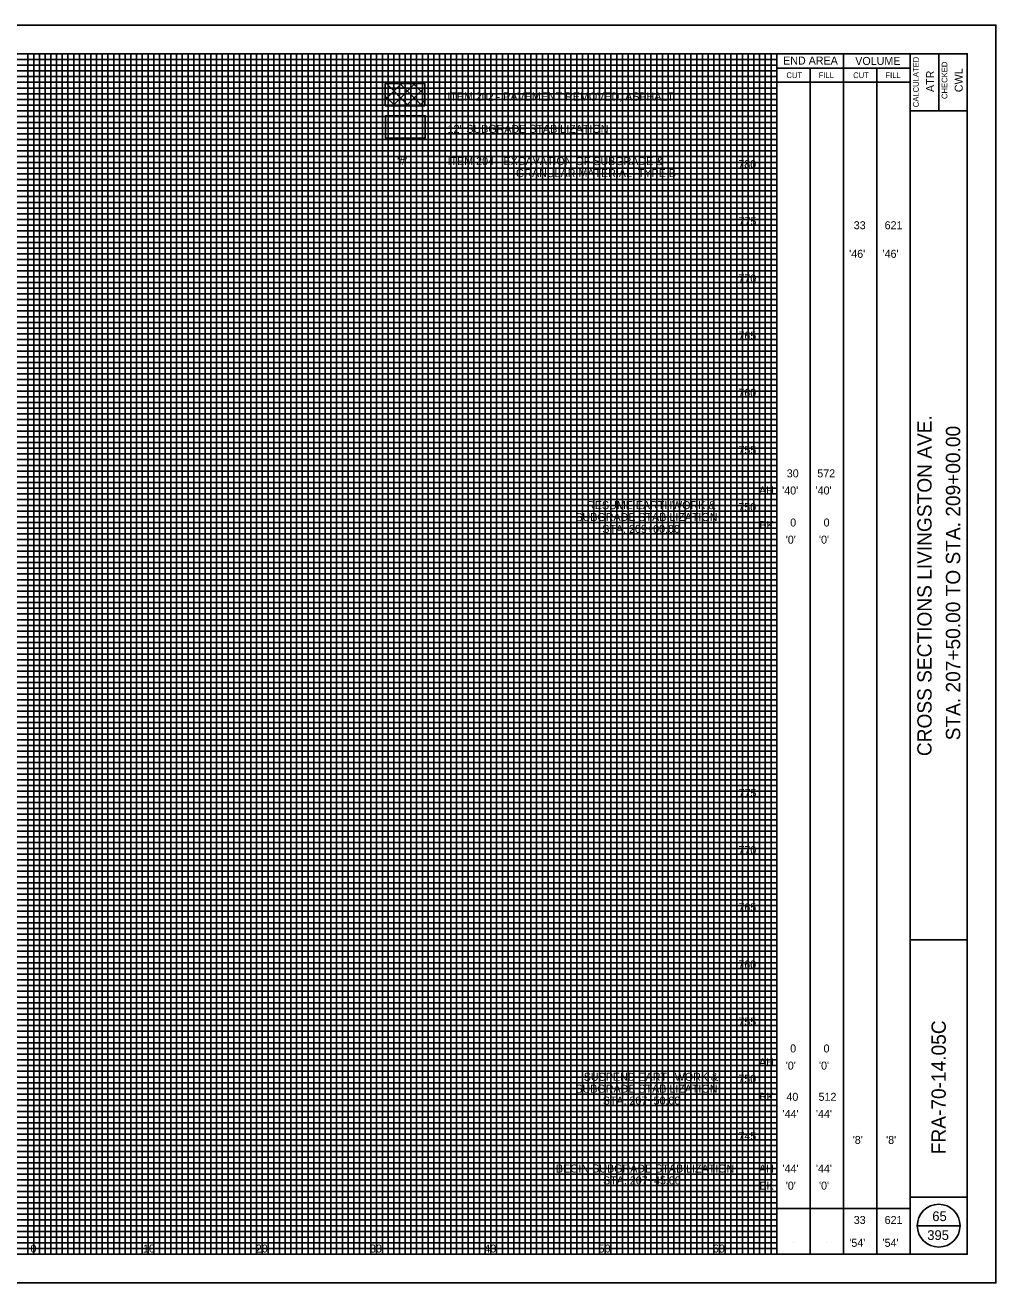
# Model space of a CAD drawing. Extents: x -10 to 160, y -2 to 568.
# Drawn here: x 75.1 to 160, y 227.5 to 337.5 of the extents above; entities that cross this region are included whole.
import ezdxf

# ---------------------------------------------------------------- set-up
doc = ezdxf.new("R2010")
doc.units = 0
for name, color, linetype in [('DR_P_Text', 7, 'Continuous'), ('SH_Border', 7, 'Continuous'), ('SH_Cut_Line', 7, 'Continuous'), ('SH_Data', 7, 'Continuous'), ('SH_Major_Grid_Line', 7, 'Continuous'), ('SH_Minor_Grid_Line', 7, 'Continuous'), ('XS_P_Annotation', 7, 'Continuous'), ('XS_P_Undercut', 7, 'Continuous'), ('XS_X_Pavt', 7, 'Continuous')]:
    doc.layers.add(name, color=color, linetype=linetype)

msp = doc.modelspace()

# ---------------------------------------------------------------- linework, layer by layer
at = {"layer": 'SH_Border'}
for p, q in [((152.5, 230), (152.5, 335)), ((155, 335), (155, 330)), ((152.5, 330), (157.5, 330)), ((152.5, 257.5), (157.5, 257.5)), ((152.5, 235), (157.5, 235))]:
    msp.add_line(p, q, dxfattribs=at)
msp.add_lwpolyline([(0, 335), (157.5, 335), (157.5, 230), (0, 230)], close=True, dxfattribs=at)
at = {"layer": 'SH_Cut_Line'}
msp.add_lwpolyline([(-10, 227.5), (160, 227.5), (160, 337.5), (-10, 337.5)], close=True, dxfattribs=at)
at = {"layer": 'SH_Data'}
for p, q in [((140.83, 230), (140.83, 335)), ((146.67, 230), (146.67, 335)), ((140.83, 333.75), (152.5, 333.75)), ((143.75, 230), (143.75, 333.75)), ((149.58, 230), (149.58, 333.75)), ((140.83, 332.5), (152.5, 332.5)), ((140.83, 234), (152.5, 234)), ((153.12, 232.5), (156.88, 232.5)), ((142.29, 231), (142.29, 231)), ((145.21, 231), (145.21, 231)), ((148.12, 231), (148.12, 231)), ((151.04, 231), (151.04, 231))]:
    msp.add_line(p, q, dxfattribs=at)
msp.add_circle((155, 232.5), 1.87, dxfattribs=at)
at = {"layer": 'SH_Major_Grid_Line'}
for p, q in [((75.83, 230), (75.83, 335)), ((80.83, 230), (80.83, 335)), ((85.83, 230), (85.83, 335)), ((90.83, 230), (90.83, 335)), ((95.83, 230), (95.83, 335)), ((100.83, 230), (100.83, 335)), ((105.83, 230), (105.83, 335)), ((110.83, 230), (110.83, 335)), ((115.83, 230), (115.83, 335)), ((120.83, 230), (120.83, 335)), ((125.83, 230), (125.83, 335)), ((130.83, 230), (130.83, 335)), ((135.83, 230), (135.83, 335)), ((5.83, 330), (140.83, 330)), ((5.83, 325), (140.83, 325)), ((5.83, 320), (140.83, 320)), ((5.83, 315), (140.83, 315)), ((5.83, 310), (140.83, 310)), ((5.83, 305), (140.83, 305)), ((5.83, 300), (140.83, 300)), ((5.83, 295), (140.83, 295)), ((5.83, 290), (140.83, 290)), ((5.83, 285), (140.83, 285)), ((5.83, 280), (140.83, 280)), ((5.83, 275), (140.83, 275)), ((5.83, 270), (140.83, 270)), ((5.83, 265), (140.83, 265)), ((5.83, 260), (140.83, 260)), ((5.83, 255), (140.83, 255)), ((5.83, 250), (140.83, 250)), ((5.83, 245), (140.83, 245)), ((5.83, 240), (140.83, 240)), ((5.83, 235), (140.83, 235))]:
    msp.add_line(p, q, dxfattribs=at)
at = {"layer": 'SH_Minor_Grid_Line'}
for p, q in [((5.83, 334.5), (140.83, 334.5)), ((75.33, 230), (75.33, 335)), ((76.33, 230), (76.33, 335)), ((76.83, 230), (76.83, 335)), ((77.33, 230), (77.33, 335)), ((77.83, 230), (77.83, 335)), ((78.33, 230), (78.33, 335)), ((78.83, 230), (78.83, 335)), ((79.33, 230), (79.33, 335)), ((79.83, 230), (79.83, 335)), ((80.33, 230), (80.33, 335)), ((81.33, 230), (81.33, 335)), ((81.83, 230), (81.83, 335)), ((82.33, 230), (82.33, 335)), ((82.83, 230), (82.83, 335)), ((83.33, 230), (83.33, 335)), ((83.83, 230), (83.83, 335)), ((84.33, 230), (84.33, 335)), ((84.83, 230), (84.83, 335)), ((85.33, 230), (85.33, 335)), ((86.33, 230), (86.33, 335)), ((86.83, 230), (86.83, 335)), ((87.33, 230), (87.33, 335)), ((87.83, 230), (87.83, 335)), ((88.33, 230), (88.33, 335)), ((88.83, 230), (88.83, 335)), ((89.33, 230), (89.33, 335)), ((89.83, 230), (89.83, 335)), ((90.33, 230), (90.33, 335)), ((91.33, 230), (91.33, 335)), ((91.83, 230), (91.83, 335)), ((92.33, 230), (92.33, 335)), ((92.83, 230), (92.83, 335)), ((93.33, 230), (93.33, 335)), ((93.83, 230), (93.83, 335)), ((94.33, 230), (94.33, 335)), ((94.83, 230), (94.83, 335)), ((95.33, 230), (95.33, 335)), ((96.33, 230), (96.33, 335)), ((96.83, 230), (96.83, 335)), ((97.33, 230), (97.33, 335)), ((97.83, 230), (97.83, 335)), ((98.33, 230), (98.33, 335)), ((98.83, 230), (98.83, 335)), ((99.33, 230), (99.33, 335)), ((99.83, 230), (99.83, 335)), ((100.33, 230), (100.33, 335)), ((101.33, 230), (101.33, 335)), ((101.83, 230), (101.83, 335)), ((102.33, 230), (102.33, 335)), ((102.83, 230), (102.83, 335)), ((103.33, 230), (103.33, 335)), ((103.83, 230), (103.83, 335)), ((104.33, 230), (104.33, 335)), ((104.83, 230), (104.83, 335)), ((105.33, 230), (105.33, 335)), ((106.33, 230), (106.33, 335)), ((106.83, 230), (106.83, 335)), ((107.33, 230), (107.33, 335)), ((107.83, 230), (107.83, 335)), ((108.33, 230), (108.33, 335)), ((108.83, 230), (108.83, 335)), ((109.33, 230), (109.33, 335)), ((109.83, 230), (109.83, 335)), ((110.33, 230), (110.33, 335)), ((111.33, 230), (111.33, 335)), ((111.83, 230), (111.83, 335)), ((112.33, 230), (112.33, 335)), ((112.83, 230), (112.83, 335)), ((113.33, 230), (113.33, 335)), ((113.83, 230), (113.83, 335)), ((114.33, 230), (114.33, 335)), ((114.83, 230), (114.83, 335)), ((115.33, 230), (115.33, 335)), ((116.33, 230), (116.33, 335)), ((116.83, 230), (116.83, 335)), ((117.33, 230), (117.33, 335)), ((117.83, 230), (117.83, 335)), ((118.33, 230), (118.33, 335)), ((118.83, 230), (118.83, 335)), ((119.33, 230), (119.33, 335)), ((119.83, 230), (119.83, 335)), ((120.33, 230), (120.33, 335)), ((121.33, 230), (121.33, 335)), ((121.83, 230), (121.83, 335)), ((122.33, 230), (122.33, 335)), ((122.83, 230), (122.83, 335)), ((123.33, 230), (123.33, 335)), ((123.83, 230), (123.83, 335)), ((124.33, 230), (124.33, 335)), ((124.83, 230), (124.83, 335)), ((125.33, 230), (125.33, 335)), ((126.33, 230), (126.33, 335)), ((126.83, 230), (126.83, 335)), ((127.33, 230), (127.33, 335)), ((127.83, 230), (127.83, 335)), ((128.33, 230), (128.33, 335)), ((128.83, 230), (128.83, 335)), ((129.33, 230), (129.33, 335)), ((129.83, 230), (129.83, 335)), ((130.33, 230), (130.33, 335)), ((131.33, 230), (131.33, 335)), ((131.83, 230), (131.83, 335)), ((132.33, 230), (132.33, 335)), ((132.83, 230), (132.83, 335)), ((133.33, 230), (133.33, 335)), ((133.83, 230), (133.83, 335)), ((134.33, 230), (134.33, 335)), ((134.83, 230), (134.83, 335)), ((135.33, 230), (135.33, 335)), ((136.33, 230), (136.33, 335)), ((136.83, 230), (136.83, 335)), ((137.33, 230), (137.33, 335)), ((137.83, 230), (137.83, 335)), ((138.33, 230), (138.33, 335)), ((138.83, 230), (138.83, 335)), ((139.33, 230), (139.33, 335)), ((139.83, 230), (139.83, 335)), ((140.33, 230), (140.33, 335)), ((5.83, 334), (140.83, 334)), ((5.83, 333.5), (140.83, 333.5)), ((5.83, 333), (140.83, 333)), ((5.83, 332.5), (140.83, 332.5)), ((5.83, 332), (140.83, 332)), ((5.83, 331.5), (140.83, 331.5)), ((5.83, 331), (140.83, 331)), ((5.83, 330.5), (140.83, 330.5)), ((5.83, 329.5), (140.83, 329.5)), ((5.83, 329), (140.83, 329)), ((5.83, 328.5), (140.83, 328.5)), ((5.83, 328), (140.83, 328)), ((5.83, 327.5), (140.83, 327.5)), ((5.83, 327), (140.83, 327)), ((5.83, 326.5), (140.83, 326.5)), ((5.83, 326), (140.83, 326)), ((5.83, 325.5), (140.83, 325.5)), ((5.83, 324.5), (140.83, 324.5)), ((5.83, 324), (140.83, 324)), ((5.83, 323.5), (140.83, 323.5)), ((5.83, 323), (140.83, 323)), ((5.83, 322.5), (140.83, 322.5)), ((5.83, 322), (140.83, 322)), ((5.83, 321.5), (140.83, 321.5)), ((5.83, 321), (140.83, 321)), ((5.83, 320.5), (140.83, 320.5)), ((5.83, 319.5), (140.83, 319.5)), ((5.83, 319), (140.83, 319)), ((5.83, 318.5), (140.83, 318.5)), ((5.83, 318), (140.83, 318)), ((5.83, 317.5), (140.83, 317.5)), ((5.83, 317), (140.83, 317)), ((5.83, 316.5), (140.83, 316.5)), ((5.83, 316), (140.83, 316)), ((5.83, 315.5), (140.83, 315.5)), ((5.83, 314.5), (140.83, 314.5)), ((5.83, 314), (140.83, 314)), ((5.83, 313.5), (140.83, 313.5)), ((5.83, 313), (140.83, 313)), ((5.83, 312.5), (140.83, 312.5)), ((5.83, 312), (140.83, 312)), ((5.83, 311.5), (140.83, 311.5)), ((5.83, 311), (140.83, 311)), ((5.83, 310.5), (140.83, 310.5)), ((5.83, 309.5), (140.83, 309.5)), ((5.83, 309), (140.83, 309)), ((5.83, 308.5), (140.83, 308.5)), ((5.83, 308), (140.83, 308)), ((5.83, 307.5), (140.83, 307.5)), ((5.83, 307), (140.83, 307)), ((5.83, 306.5), (140.83, 306.5)), ((5.83, 306), (140.83, 306)), ((5.83, 305.5), (140.83, 305.5)), ((5.83, 304.5), (140.83, 304.5)), ((5.83, 304), (140.83, 304)), ((5.83, 303.5), (140.83, 303.5)), ((5.83, 303), (140.83, 303)), ((5.83, 302.5), (140.83, 302.5)), ((5.83, 302), (140.83, 302)), ((5.83, 301.5), (140.83, 301.5)), ((5.83, 301), (140.83, 301)), ((5.83, 300.5), (140.83, 300.5)), ((5.83, 299.5), (140.83, 299.5)), ((5.83, 299), (140.83, 299)), ((5.83, 298.5), (140.83, 298.5)), ((5.83, 298), (140.83, 298)), ((5.83, 297.5), (140.83, 297.5)), ((5.83, 297), (140.83, 297)), ((5.83, 296.5), (140.83, 296.5)), ((5.83, 296), (140.83, 296)), ((5.83, 295.5), (140.83, 295.5)), ((5.83, 294.5), (140.83, 294.5)), ((5.83, 294), (140.83, 294)), ((5.83, 293.5), (140.83, 293.5)), ((5.83, 293), (140.83, 293)), ((5.83, 292.5), (140.83, 292.5)), ((5.83, 292), (140.83, 292)), ((5.83, 291.5), (140.83, 291.5)), ((5.83, 291), (140.83, 291)), ((5.83, 290.5), (140.83, 290.5)), ((5.83, 289.5), (140.83, 289.5)), ((5.83, 289), (140.83, 289)), ((5.83, 288.5), (140.83, 288.5)), ((5.83, 288), (140.83, 288)), ((5.83, 287.5), (140.83, 287.5)), ((5.83, 287), (140.83, 287)), ((5.83, 286.5), (140.83, 286.5)), ((5.83, 286), (140.83, 286)), ((5.83, 285.5), (140.83, 285.5)), ((5.83, 284.5), (140.83, 284.5)), ((5.83, 284), (140.83, 284)), ((5.83, 283.5), (140.83, 283.5)), ((5.83, 283), (140.83, 283)), ((5.83, 282.5), (140.83, 282.5)), ((5.83, 282), (140.83, 282)), ((5.83, 281.5), (140.83, 281.5)), ((5.83, 281), (140.83, 281)), ((5.83, 280.5), (140.83, 280.5)), ((5.83, 279.5), (140.83, 279.5)), ((5.83, 279), (140.83, 279)), ((5.83, 278.5), (140.83, 278.5)), ((5.83, 278), (140.83, 278)), ((5.83, 277.5), (140.83, 277.5)), ((5.83, 277), (140.83, 277)), ((5.83, 276.5), (140.83, 276.5)), ((5.83, 276), (140.83, 276)), ((5.83, 275.5), (140.83, 275.5)), ((5.83, 274.5), (140.83, 274.5)), ((5.83, 274), (140.83, 274)), ((5.83, 273.5), (140.83, 273.5)), ((5.83, 273), (140.83, 273)), ((5.83, 272.5), (140.83, 272.5)), ((5.83, 272), (140.83, 272)), ((5.83, 271.5), (140.83, 271.5)), ((5.83, 271), (140.83, 271)), ((5.83, 270.5), (140.83, 270.5)), ((5.83, 269.5), (140.83, 269.5)), ((5.83, 269), (140.83, 269)), ((5.83, 268.5), (140.83, 268.5)), ((5.83, 268), (140.83, 268)), ((5.83, 267.5), (140.83, 267.5)), ((5.83, 267), (140.83, 267)), ((5.83, 266.5), (140.83, 266.5)), ((5.83, 266), (140.83, 266)), ((5.83, 265.5), (140.83, 265.5)), ((5.83, 264.5), (140.83, 264.5)), ((5.83, 264), (140.83, 264)), ((5.83, 263.5), (140.83, 263.5)), ((5.83, 263), (140.83, 263)), ((5.83, 262.5), (140.83, 262.5)), ((5.83, 262), (140.83, 262)), ((5.83, 261.5), (140.83, 261.5)), ((5.83, 261), (140.83, 261)), ((5.83, 260.5), (140.83, 260.5)), ((5.83, 259.5), (140.83, 259.5)), ((5.83, 259), (140.83, 259)), ((5.83, 258.5), (140.83, 258.5)), ((5.83, 258), (140.83, 258)), ((5.83, 257.5), (140.83, 257.5)), ((5.83, 257), (140.83, 257)), ((5.83, 256.5), (140.83, 256.5)), ((5.83, 256), (140.83, 256)), ((5.83, 255.5), (140.83, 255.5)), ((5.83, 254.5), (140.83, 254.5)), ((5.83, 254), (140.83, 254)), ((5.83, 253.5), (140.83, 253.5)), ((5.83, 253), (140.83, 253)), ((5.83, 252.5), (140.83, 252.5)), ((5.83, 252), (140.83, 252)), ((5.83, 251.5), (140.83, 251.5)), ((5.83, 251), (140.83, 251)), ((5.83, 250.5), (140.83, 250.5)), ((5.83, 249.5), (140.83, 249.5)), ((5.83, 249), (140.83, 249)), ((5.83, 248.5), (140.83, 248.5)), ((5.83, 248), (140.83, 248)), ((5.83, 247.5), (140.83, 247.5)), ((5.83, 247), (140.83, 247)), ((5.83, 246.5), (140.83, 246.5)), ((5.83, 246), (140.83, 246)), ((5.83, 245.5), (140.83, 245.5)), ((5.83, 244.5), (140.83, 244.5)), ((5.83, 244), (140.83, 244)), ((5.83, 243.5), (140.83, 243.5)), ((5.83, 243), (140.83, 243)), ((5.83, 242.5), (140.83, 242.5)), ((5.83, 242), (140.83, 242)), ((5.83, 241.5), (140.83, 241.5)), ((5.83, 241), (140.83, 241)), ((5.83, 240.5), (140.83, 240.5)), ((5.83, 239.5), (140.83, 239.5)), ((5.83, 239), (140.83, 239)), ((5.83, 238.5), (140.83, 238.5)), ((5.83, 238), (140.83, 238)), ((5.83, 237.5), (140.83, 237.5)), ((5.83, 237), (140.83, 237)), ((5.83, 236.5), (140.83, 236.5)), ((5.83, 236), (140.83, 236)), ((5.83, 235.5), (140.83, 235.5)), ((5.83, 234.5), (140.83, 234.5)), ((5.83, 234), (140.83, 234)), ((5.83, 233.5), (140.83, 233.5)), ((5.83, 233), (140.83, 233)), ((5.83, 232.5), (140.83, 232.5)), ((5.83, 232), (140.83, 232)), ((5.83, 231.5), (140.83, 231.5)), ((5.83, 231), (140.83, 231)), ((5.83, 230.5), (140.83, 230.5))]:
    msp.add_line(p, q, dxfattribs=at)
at = {"layer": 'XS_P_Annotation'}
for points in [[(106.59, 332.39), (110.05, 332.39), (110.05, 330.45), (106.59, 330.45)], [(106.61, 329.57), (110.08, 329.57), (110.08, 327.62), (106.61, 327.62)]]:
    msp.add_lwpolyline(points, close=True, dxfattribs=at)
at = {"layer": 'XS_P_Undercut'}
msp.add_lwpolyline([(106.61, 327.62), (110.08, 327.62), (110.08, 329.57), (106.61, 329.57), (106.61, 327.62)], dxfattribs=at)
at = {"layer": 'XS_X_Pavt'}
for p, q in [((106.59, 330.97), (108, 332.39)), ((106.68, 332.39), (108.62, 330.45)), ((107.24, 330.45), (109.18, 332.39)), ((107.85, 332.39), (109.8, 330.45)), ((109.03, 332.39), (110.05, 331.37)), ((106.59, 331.3), (107.44, 330.45)), ((108.42, 330.45), (110.05, 332.09)), ((109.59, 330.45), (110.05, 330.91))]:
    msp.add_line(p, q, dxfattribs=at)

# ---------------------------------------------------------------- texts
at = {"layer": 'DR_P_Text'}
for s, p in [("'#'", (107.62, 325.26)), ('780', (137.47, 325)), ('775', (137.49, 320)), ('33', (147.57, 319.65)), ('621', (150.27, 319.65)), ("'46'", (147.17, 317.15)), ("'46'", (150.09, 317.15)), ('770', (137.48, 315)), ('765', (137.48, 310)), ('760', (137.47, 305)), ('755', (137.48, 300)), ('30', (141.71, 297.95)), ('572', (144.38, 297.95)), ('AH', (139.28, 296.45)), ("'40'", (141.31, 296.45)), ("'40'", (144.23, 296.45)), ('750', (137.47, 295)), ('BK', (139.32, 293.42)), ('0', (142.01, 293.65)), ('0', (144.93, 293.65)), ("'0'", (141.62, 292.15)), ("'0'", (144.53, 292.15)), ('775', (137.49, 270)), ('770', (137.48, 265)), ('765', (137.48, 260)), ('760', (137.47, 255)), ('755', (137.48, 250)), ('0', (142.01, 247.65)), ('0', (144.93, 247.65)), ('AH', (139.28, 246.45)), ("'0'", (141.62, 246.15)), ("'0'", (144.53, 246.15)), ('750', (137.47, 245)), ('BK', (139.32, 243.42)), ('40', (141.68, 243.42)), ('512', (144.49, 243.42)), ("'44'", (141.34, 241.92)), ("'44'", (144.26, 241.92)), ('745', (137.48, 240)), ("'8'", (147.48, 239.65)), ("'8'", (150.4, 239.65)), ('AH', (139.28, 237.15)), ("'44'", (141.34, 237.15)), ("'44'", (144.26, 237.15)), ('BK', (139.32, 235.65)), ("'0'", (141.62, 235.65)), ("'0'", (144.53, 235.65)), ('33', (147.57, 232.65)), ('621', (150.27, 232.65)), ("'54'", (147.18, 230.65)), ("'54'", (150.09, 230.65)), ('0', (75.55, 230.15)), ('0', (75.55, 230.15)), ('10', (85.39, 230.15)), ('20', (95.26, 230.15)), ('30', (105.25, 230.15)), ('40', (115.25, 230.15)), ('50', (125.25, 230.15)), ('60', (135.25, 230.15))]:
    msp.add_text(s, height=0.7, dxfattribs=at).set_placement(p)
at = {"layer": 'SH_Data'}
for s, height, p in [('END AREA', 0.7, (141.39, 334.05)), ('VOLUME', 0.7, (147.7, 334.02)), ('CUT', 0.5, (141.68, 332.87)), ('FILL', 0.5, (144.5, 332.87)), ('CUT', 0.5, (147.52, 332.87)), ('FILL', 0.5, (150.34, 332.87)), ('65', 0.85, (154.44, 232.9)), ('395', 0.85, (154, 231.25))]:
    msp.add_text(s, height=height, dxfattribs=at).set_placement(p)
for s, height, p in [('CALCULATED', 0.5, (153.26, 330.32)), ('ATR', 0.7, (154.6, 331.65)), ('CHECKED', 0.5, (155.76, 331.04)), ('CWL', 0.7, (157.1, 331.64)), ('CROSS SECTIONS LIVINGSTON AVE.', 1.25, (154.38, 273.57)), ('STA. 207+50.00 TO STA. 209+00.00', 1.25, (156.88, 274.95)), ('FRA-70-14.05C', 1.25, (155.62, 238.75))]:
    msp.add_text(s, height=height, rotation=90, dxfattribs=at).set_placement(p)
at = {"layer": 'XS_P_Annotation'}
for s, p in [('ITEM 202 - PAVEMENT REMOVED, ASPHALT', (112.02, 330.91)), ('12" SUBGRADE STABILIZATION', (112.04, 328.08)), ('ITEM 204 - EXCAVATION OF SUBGRADE &', (112.04, 325.26)), ('GRANULAR MATERIAL, TYPE B', (118.02, 324.21)), ('SUBGRADE STABILIZATION', (123.22, 294.13)), ('RESUME EARTHWORK &', (124.24, 295.17)), ('STA. 209+00.00', (125.57, 293.09)), ('SUSPEND EARTHWORK &', (123.95, 245.17)), ('SUBGRADE STABILIZATION', (123.22, 244.13)), ('STA. 207+50.00', (125.61, 243.09)), ('BEGIN SUBGRADE STABILIZATION', (121.51, 237.15)), ('STA. 207+45.00', (125.64, 236.11))]:
    msp.add_text(s, height=0.7, dxfattribs=at).set_placement(p)

doc.saveas('drawing.dxf')
